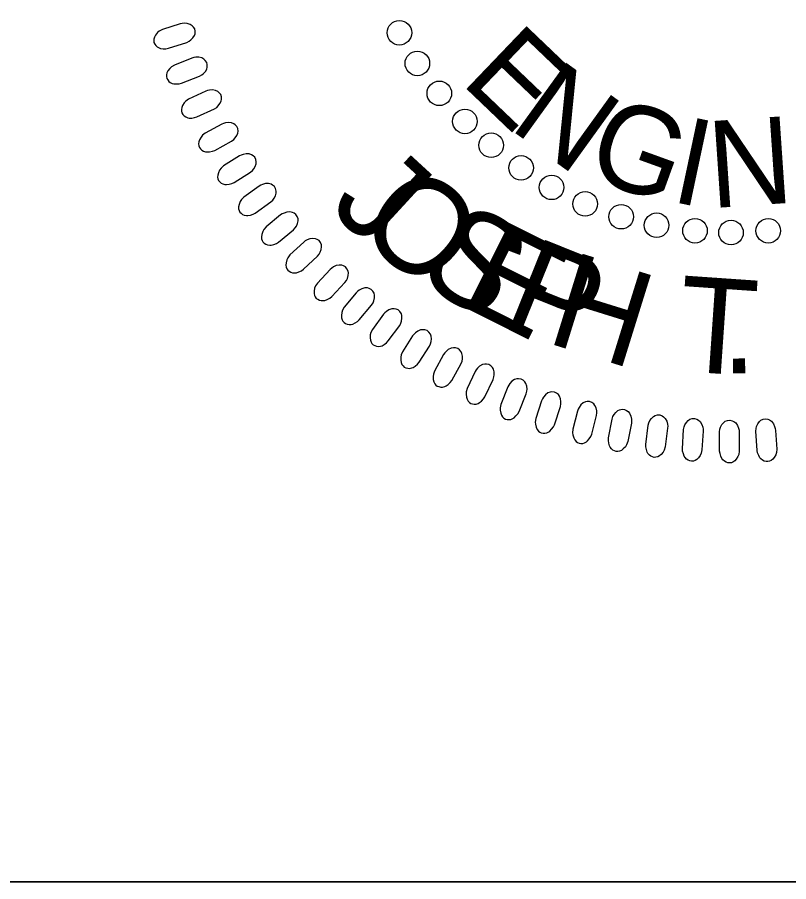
# Model space of a CAD drawing. Extents: x 1487909 to 1489267, y 497866 to 499814.
# Drawn here: x 1489041.143 to 1489045.319, y 498441.698 to 498446.38 of the extents above; entities that cross this region are included whole.
import ezdxf

# ---------------------------------------------------------------- set-up
doc = ezdxf.new("R2010")
doc.units = 0
for name, color, linetype in [('Old_Level_9', 7, 'Continuous'), ('Sheet Sticker Exception Certification CELL', 7, 'Continuous'), ('Sheet Typical CELL', 7, 'Continuous')]:
    doc.layers.add(name, color=color, linetype=linetype)

msp = doc.modelspace()

# ---------------------------------------------------------------- linework, layer by layer
at = {"layer": 'Old_Level_9'}
for points in [[(1489042.0249, 498446.3449), (1489041.928, 498446.3134), (1489041.9116, 498446.3049), (1489041.9019, 498446.2972), (1489041.8914, 498446.284), (1489041.8853, 498446.2735), (1489041.8818, 498446.2626), (1489041.8814, 498446.2533), (1489041.8827, 498446.244), (1489041.8871, 498446.2357), (1489041.8926, 498446.227), (1489041.8999, 498446.2202), (1489041.9105, 498446.2146), (1489041.9183, 498446.2118), (1489041.9319, 498446.2104), (1489041.9476, 498446.2103), (1489041.9608, 498446.2126), (1489042.0602, 498446.2442), (1489042.0729, 498446.2503), (1489042.0828, 498446.2574), (1489042.0931, 498446.2686), (1489042.1012, 498446.281), (1489042.1051, 498446.2907), (1489042.1058, 498446.3046), (1489042.1035, 498446.317), (1489042.0965, 498446.3277), (1489042.0899, 498446.3347), (1489042.0788, 498446.3422), (1489042.0624, 498446.3473), (1489042.0465, 498446.348), (1489042.0355, 498446.347)], [(1489042.0878, 498446.1592), (1489041.9931, 498446.1218), (1489041.9773, 498446.1122), (1489041.9681, 498446.1039), (1489041.9585, 498446.0901), (1489041.953, 498446.0792), (1489041.9503, 498446.0681), (1489041.9504, 498446.0589), (1489041.9522, 498446.0495), (1489041.9572, 498446.0416), (1489041.9632, 498446.0332), (1489041.9709, 498446.027), (1489041.9819, 498446.0219), (1489041.9898, 498446.0197), (1489042.0035, 498446.0191), (1489042.0191, 498446.02), (1489042.0321, 498446.0231), (1489042.1294, 498446.0609), (1489042.1418, 498446.0678), (1489042.1512, 498446.0755), (1489042.1607, 498446.0873), (1489042.1681, 498446.1002), (1489042.1713, 498446.1102), (1489042.1711, 498446.1241), (1489042.1681, 498446.1363), (1489042.1605, 498446.1466), (1489042.1534, 498446.1531), (1489042.1418, 498446.1599), (1489042.1251, 498446.1639), (1489042.1092, 498446.1637), (1489042.0983, 498446.162)], [(1489042.1625, 498445.98), (1489042.0703, 498445.9367), (1489042.0552, 498445.9261), (1489042.0465, 498445.9173), (1489042.0378, 498445.9028), (1489042.0329, 498445.8916), (1489042.0309, 498445.8804), (1489042.0316, 498445.8711), (1489042.0341, 498445.862), (1489042.0396, 498445.8543), (1489042.0461, 498445.8464), (1489042.0542, 498445.8406), (1489042.0654, 498445.8363), (1489042.0735, 498445.8346), (1489042.0871, 498445.8348), (1489042.1027, 498445.8367), (1489042.1155, 498445.8406), (1489042.2102, 498445.8844), (1489042.2221, 498445.8922), (1489042.231, 498445.9004), (1489042.2398, 498445.9128), (1489042.2464, 498445.9261), (1489042.2489, 498445.9363), (1489042.2479, 498445.9502), (1489042.2441, 498445.9622), (1489042.2358, 498445.9719), (1489042.2283, 498445.978), (1489042.2164, 498445.9841), (1489042.1994, 498445.987), (1489042.1835, 498445.9858), (1489042.1728, 498445.9834)], [(1489042.2494, 498445.8016), (1489042.1601, 498445.7526), (1489042.1457, 498445.7411), (1489042.1376, 498445.7317), (1489042.1298, 498445.7168), (1489042.1257, 498445.7053), (1489042.1244, 498445.694), (1489042.1256, 498445.6848), (1489042.1287, 498445.6758), (1489042.1346, 498445.6685), (1489042.1416, 498445.661), (1489042.1501, 498445.6558), (1489042.1616, 498445.6522), (1489042.1697, 498445.651), (1489042.1833, 498445.6521), (1489042.1987, 498445.6549), (1489042.2113, 498445.6596), (1489042.303, 498445.7093), (1489042.3144, 498445.7177), (1489042.3228, 498445.7266), (1489042.3308, 498445.7395), (1489042.3364, 498445.7532), (1489042.3384, 498445.7635), (1489042.3365, 498445.7772), (1489042.3319, 498445.789), (1489042.323, 498445.7982), (1489042.3152, 498445.8039), (1489042.3029, 498445.8091), (1489042.2858, 498445.811), (1489042.27, 498445.8087), (1489042.2594, 498445.8057)], [(1489042.3454, 498445.6295), (1489042.2594, 498445.5749), (1489042.2457, 498445.5626), (1489042.2382, 498445.5527), (1489042.2313, 498445.5372), (1489042.2279, 498445.5256), (1489042.2273, 498445.5142), (1489042.2292, 498445.5051), (1489042.2328, 498445.4963), (1489042.2392, 498445.4894), (1489042.2466, 498445.4823), (1489042.2554, 498445.4776), (1489042.2671, 498445.4747), (1489042.2753, 498445.4741), (1489042.2888, 498445.476), (1489042.304, 498445.4798), (1489042.3162, 498445.4853), (1489042.4046, 498445.5406), (1489042.4155, 498445.5497), (1489042.4233, 498445.5592), (1489042.4305, 498445.5725), (1489042.4353, 498445.5866), (1489042.4366, 498445.5969), (1489042.4338, 498445.6106), (1489042.4285, 498445.622), (1489042.4191, 498445.6307), (1489042.411, 498445.6357), (1489042.3983, 498445.6403), (1489042.3811, 498445.6411), (1489042.3655, 498445.6378), (1489042.3551, 498445.6341)], [(1489042.4514, 498445.4655), (1489042.3689, 498445.4057), (1489042.356, 498445.3925), (1489042.3491, 498445.3822), (1489042.3433, 498445.3664), (1489042.3407, 498445.3545), (1489042.3408, 498445.3431), (1489042.3432, 498445.3341), (1489042.3473, 498445.3255), (1489042.3541, 498445.319), (1489042.362, 498445.3124), (1489042.3711, 498445.3083), (1489042.3829, 498445.3062), (1489042.3912, 498445.3061), (1489042.4045, 498445.3088), (1489042.4194, 498445.3136), (1489042.4313, 498445.3198), (1489042.516, 498445.3806), (1489042.5263, 498445.3904), (1489042.5335, 498445.4002), (1489042.5399, 498445.414), (1489042.5438, 498445.4283), (1489042.5444, 498445.4388), (1489042.5408, 498445.4522), (1489042.5348, 498445.4633), (1489042.5248, 498445.4713), (1489042.5164, 498445.4759), (1489042.5035, 498445.4797), (1489042.4863, 498445.4794), (1489042.4709, 498445.4751), (1489042.4608, 498445.4708)], [(1489042.5678, 498445.3094), (1489042.4893, 498445.2445), (1489042.4773, 498445.2305), (1489042.4711, 498445.2198), (1489042.4662, 498445.2036), (1489042.4643, 498445.1916), (1489042.4652, 498445.1802), (1489042.4681, 498445.1714), (1489042.4728, 498445.1632), (1489042.48, 498445.1571), (1489042.4883, 498445.151), (1489042.4976, 498445.1475), (1489042.5095, 498445.1461), (1489042.5178, 498445.1465), (1489042.5309, 498445.1501), (1489042.5455, 498445.1557), (1489042.5569, 498445.1627), (1489042.6378, 498445.2287), (1489042.6474, 498445.2391), (1489042.6539, 498445.2494), (1489042.6594, 498445.2635), (1489042.6624, 498445.2781), (1489042.6624, 498445.2885), (1489042.6579, 498445.3017), (1489042.6513, 498445.3124), (1489042.6408, 498445.3198), (1489042.6321, 498445.3238), (1489042.619, 498445.3267), (1489042.6018, 498445.3254), (1489042.5867, 498445.3202), (1489042.5769, 498445.3153)], [(1489042.6932, 498445.1624), (1489042.6189, 498445.0927), (1489042.6078, 498445.078), (1489042.6023, 498445.0669), (1489042.5984, 498445.0505), (1489042.5973, 498445.0384), (1489042.5988, 498445.0271), (1489042.6023, 498445.0184), (1489042.6075, 498445.0105), (1489042.6151, 498445.0049), (1489042.6237, 498444.9994), (1489042.6332, 498444.9964), (1489042.6452, 498444.9958), (1489042.6534, 498444.9967), (1489042.6664, 498445.0011), (1489042.6806, 498445.0077), (1489042.6915, 498445.0153), (1489042.768, 498445.0863), (1489042.777, 498445.0973), (1489042.7829, 498445.1079), (1489042.7875, 498445.1224), (1489042.7896, 498445.1371), (1489042.7888, 498445.1475), (1489042.7836, 498445.1605), (1489042.7762, 498445.1706), (1489042.7654, 498445.1774), (1489042.7564, 498445.1809), (1489042.7431, 498445.1829), (1489042.7261, 498445.1805), (1489042.7114, 498445.1744), (1489042.7019, 498445.1688)], [(1489042.8372, 498445.0148), (1489042.7675, 498444.9406), (1489042.7573, 498444.9252), (1489042.7525, 498444.9138), (1489042.7496, 498444.8972), (1489042.7493, 498444.8849), (1489042.7515, 498444.8738), (1489042.7556, 498444.8655), (1489042.7612, 498444.8579), (1489042.7691, 498444.8527), (1489042.7781, 498444.8477), (1489042.7878, 498444.8454), (1489042.7998, 498444.8455), (1489042.8079, 498444.8469), (1489042.8206, 498444.8521), (1489042.8343, 498444.8596), (1489042.8448, 498444.8679), (1489042.9167, 498444.9436), (1489042.9249, 498444.9551), (1489042.9302, 498444.9661), (1489042.9338, 498444.9808), (1489042.935, 498444.9956), (1489042.9336, 498445.006), (1489042.9276, 498445.0185), (1489042.9196, 498445.0283), (1489042.9083, 498445.0343), (1489042.8991, 498445.0372), (1489042.8858, 498445.0385), (1489042.8689, 498445.035), (1489042.8546, 498445.0279), (1489042.8454, 498445.0218)], [(1489042.9775, 498444.8878), (1489042.9125, 498444.8094), (1489042.9033, 498444.7933), (1489042.8992, 498444.7817), (1489042.8975, 498444.7649), (1489042.8979, 498444.7527), (1489042.9008, 498444.7417), (1489042.9054, 498444.7336), (1489042.9115, 498444.7263), (1489042.9197, 498444.7218), (1489042.929, 498444.7173), (1489042.9388, 498444.7156), (1489042.9508, 498444.7165), (1489042.9588, 498444.7184), (1489042.9711, 498444.7244), (1489042.9844, 498444.7327), (1489042.9943, 498444.7417), (1489043.0612, 498444.8217), (1489043.0688, 498444.8337), (1489043.0733, 498444.845), (1489043.076, 498444.8599), (1489043.0763, 498444.8748), (1489043.0742, 498444.8851), (1489043.0674, 498444.8972), (1489043.0588, 498444.9064), (1489043.0472, 498444.9117), (1489043.0378, 498444.9141), (1489043.0245, 498444.9144), (1489043.0079, 498444.9099), (1489042.994, 498444.902), (1489042.9853, 498444.8953)], [(1489043.1253, 498444.7716), (1489043.0654, 498444.6892), (1489043.0572, 498444.6726), (1489043.0539, 498444.6607), (1489043.0531, 498444.6438), (1489043.0544, 498444.6317), (1489043.058, 498444.6209), (1489043.063, 498444.6131), (1489043.0696, 498444.6063), (1489043.0781, 498444.6022), (1489043.0876, 498444.5984), (1489043.0976, 498444.5972), (1489043.1094, 498444.5989), (1489043.1173, 498444.6013), (1489043.1292, 498444.6081), (1489043.1419, 498444.6172), (1489043.1512, 498444.6268), (1489043.213, 498444.7108), (1489043.2198, 498444.7232), (1489043.2236, 498444.7349), (1489043.2254, 498444.7499), (1489043.2247, 498444.7648), (1489043.2221, 498444.7748), (1489043.2145, 498444.7866), (1489043.2054, 498444.7952), (1489043.1934, 498444.7998), (1489043.1839, 498444.8015), (1489043.1705, 498444.8011), (1489043.1543, 498444.7955), (1489043.1409, 498444.7867), (1489043.1326, 498444.7795)], [(1489043.2832, 498444.6543), (1489043.2286, 498444.5683), (1489043.2214, 498444.5513), (1489043.2188, 498444.5392), (1489043.2191, 498444.5223), (1489043.2211, 498444.5103), (1489043.2254, 498444.4997), (1489043.2309, 498444.4922), (1489043.2379, 498444.4859), (1489043.2466, 498444.4823), (1489043.2564, 498444.479), (1489043.2664, 498444.4786), (1489043.2781, 498444.4809), (1489043.2859, 498444.4839), (1489043.2973, 498444.4913), (1489043.3094, 498444.5012), (1489043.3181, 498444.5114), (1489043.3745, 498444.5991), (1489043.3805, 498444.612), (1489043.3835, 498444.6238), (1489043.3844, 498444.639), (1489043.3828, 498444.6537), (1489043.3794, 498444.6637), (1489043.3712, 498444.6749), (1489043.3616, 498444.6829), (1489043.3493, 498444.6867), (1489043.3397, 498444.6879), (1489043.3264, 498444.6866), (1489043.3105, 498444.68), (1489043.2978, 498444.6704), (1489043.2899, 498444.6627)], [(1489043.4506, 498444.5534), (1489043.4015, 498444.4642), (1489043.3955, 498444.4467), (1489043.3937, 498444.4345), (1489043.3951, 498444.4177), (1489043.3977, 498444.4058), (1489043.4027, 498444.3955), (1489043.4087, 498444.3884), (1489043.4161, 498444.3825), (1489043.425, 498444.3795), (1489043.4349, 498444.3768), (1489043.4449, 498444.3769), (1489043.4565, 498444.3801), (1489043.464, 498444.3834), (1489043.475, 498444.3917), (1489043.4865, 498444.4023), (1489043.4945, 498444.413), (1489043.5453, 498444.5041), (1489043.5504, 498444.5173), (1489043.5528, 498444.5293), (1489043.5526, 498444.5445), (1489043.5501, 498444.5591), (1489043.5462, 498444.5688), (1489043.5372, 498444.5794), (1489043.5271, 498444.5869), (1489043.5147, 498444.5899), (1489043.505, 498444.5905), (1489043.4918, 498444.5884), (1489043.4763, 498444.5808), (1489043.4642, 498444.5704), (1489043.4569, 498444.5622)], [(1489043.6216, 498444.4615), (1489043.5782, 498444.3694), (1489043.5732, 498444.3516), (1489043.5722, 498444.3393), (1489043.5746, 498444.3226), (1489043.578, 498444.3109), (1489043.5837, 498444.301), (1489043.5901, 498444.2943), (1489043.5978, 498444.2888), (1489043.6069, 498444.2864), (1489043.617, 498444.2844), (1489043.6269, 498444.2851), (1489043.6384, 498444.289), (1489043.6457, 498444.2928), (1489043.656, 498444.3017), (1489043.6669, 498444.313), (1489043.6742, 498444.3242), (1489043.7192, 498444.4183), (1489043.7235, 498444.4319), (1489043.725, 498444.4439), (1489043.724, 498444.4591), (1489043.7205, 498444.4735), (1489043.716, 498444.4829), (1489043.7063, 498444.493), (1489043.6958, 498444.4998), (1489043.6832, 498444.5021), (1489043.6735, 498444.502), (1489043.6605, 498444.4991), (1489043.6455, 498444.4905), (1489043.6341, 498444.4794), (1489043.6273, 498444.4707)], [(1489043.7982, 498444.3779), (1489043.7606, 498444.2832), (1489043.7568, 498444.2651), (1489043.7565, 498444.2528), (1489043.76, 498444.2362), (1489043.7641, 498444.2248), (1489043.7704, 498444.2152), (1489043.7772, 498444.2089), (1489043.7853, 498444.2039), (1489043.7945, 498444.2021), (1489043.8047, 498444.2007), (1489043.8146, 498444.2021), (1489043.8257, 498444.2067), (1489043.8328, 498444.211), (1489043.8425, 498444.2205), (1489043.8526, 498444.2325), (1489043.8593, 498444.2441), (1489043.8983, 498444.3408), (1489043.9017, 498444.3546), (1489043.9025, 498444.3667), (1489043.9005, 498444.3818), (1489043.8961, 498444.396), (1489043.891, 498444.4051), (1489043.8808, 498444.4146), (1489043.8698, 498444.4207), (1489043.8571, 498444.4221), (1489043.8475, 498444.4215), (1489043.8346, 498444.4177), (1489043.8202, 498444.4083), (1489043.8095, 498444.3964), (1489043.8033, 498444.3874)], [(1489043.9815, 498444.303), (1489043.95, 498444.2062), (1489043.9473, 498444.1879), (1489043.9478, 498444.1755), (1489043.9523, 498444.1592), (1489043.9571, 498444.1481), (1489043.964, 498444.1389), (1489043.9712, 498444.1331), (1489043.9795, 498444.1286), (1489043.9889, 498444.1274), (1489043.9991, 498444.1266), (1489044.0089, 498444.1286), (1489044.0197, 498444.1339), (1489044.0265, 498444.1386), (1489044.0357, 498444.1487), (1489044.045, 498444.1613), (1489044.0509, 498444.1733), (1489044.0837, 498444.2723), (1489044.0863, 498444.2863), (1489044.0863, 498444.2985), (1489044.0833, 498444.3133), (1489044.0781, 498444.3272), (1489044.0724, 498444.3361), (1489044.0616, 498444.3448), (1489044.0503, 498444.3502), (1489044.0375, 498444.3509), (1489044.0279, 498444.3496), (1489044.0153, 498444.3451), (1489044.0016, 498444.3347), (1489043.9916, 498444.3223), (1489043.986, 498444.3128)], [(1489044.1751, 498444.2471), (1489044.1497, 498444.1485), (1489044.1482, 498444.1302), (1489044.1495, 498444.1178), (1489044.155, 498444.1018), (1489044.1605, 498444.091), (1489044.168, 498444.0823), (1489044.1755, 498444.0769), (1489044.1841, 498444.073), (1489044.1935, 498444.0723), (1489044.2038, 498444.0723), (1489044.2134, 498444.0748), (1489044.2239, 498444.0807), (1489044.2304, 498444.0859), (1489044.2388, 498444.0965), (1489044.2474, 498444.1097), (1489044.2525, 498444.1221), (1489044.2791, 498444.2229), (1489044.2807, 498444.237), (1489044.28, 498444.2492), (1489044.2761, 498444.2639), (1489044.27, 498444.2774), (1489044.2638, 498444.2858), (1489044.2524, 498444.2939), (1489044.2408, 498444.2986), (1489044.2279, 498444.2985), (1489044.2185, 498444.2966), (1489044.2062, 498444.2913), (1489044.1932, 498444.2801), (1489044.184, 498444.267), (1489044.179, 498444.2572)], [(1489044.4674, 498444.1818), (1489044.4483, 498444.0817), (1489044.4418, 498444.0644), (1489044.4354, 498444.0538), (1489044.4236, 498444.0418), (1489044.414, 498444.0344), (1489044.4036, 498444.0296), (1489044.3945, 498444.028), (1489044.385, 498444.0281), (1489044.3762, 498444.0315), (1489044.3669, 498444.0358), (1489044.3593, 498444.0423), (1489044.3523, 498444.052), (1489044.3487, 498444.0595), (1489044.3455, 498444.0727), (1489044.3434, 498444.0883), (1489044.3441, 498444.1017), (1489044.3631, 498444.2042), (1489044.3676, 498444.2177), (1489044.3734, 498444.2284), (1489044.3832, 498444.24), (1489044.3945, 498444.2496), (1489044.4037, 498444.2546), (1489044.4173, 498444.257), (1489044.4299, 498444.2563), (1489044.4414, 498444.2507), (1489044.4492, 498444.245), (1489044.458, 498444.235), (1489044.4651, 498444.2193), (1489044.4678, 498444.2036), (1489044.4682, 498444.1926)], [(1489044.6638, 498444.1547), (1489044.651, 498444.0537), (1489044.6456, 498444.036), (1489044.6399, 498444.025), (1489044.6289, 498444.0122), (1489044.6197, 498444.0042), (1489044.6097, 498443.9988), (1489044.6006, 498443.9966), (1489044.5912, 498443.9962), (1489044.5822, 498443.999), (1489044.5726, 498444.0027), (1489044.5646, 498444.0087), (1489044.5571, 498444.018), (1489044.553, 498444.0252), (1489044.549, 498444.0383), (1489044.5459, 498444.0536), (1489044.5458, 498444.067), (1489044.5582, 498444.1705), (1489044.5619, 498444.1842), (1489044.5671, 498444.1953), (1489044.576, 498444.2075), (1489044.5867, 498444.2178), (1489044.5956, 498444.2234), (1489044.6091, 498444.2267), (1489044.6217, 498444.2267), (1489044.6335, 498444.2219), (1489044.6417, 498444.2167), (1489044.6511, 498444.2072), (1489044.6591, 498444.192), (1489044.6628, 498444.1765), (1489044.6639, 498444.1655)], [(1489044.8561, 498444.1383), (1489044.8497, 498444.0367), (1489044.8455, 498444.0187), (1489044.8404, 498444.0074), (1489044.8302, 498443.9939), (1489044.8216, 498443.9853), (1489044.8119, 498443.9794), (1489044.803, 498443.9766), (1489044.7936, 498443.9755), (1489044.7845, 498443.9778), (1489044.7747, 498443.9809), (1489044.7664, 498443.9863), (1489044.7582, 498443.9952), (1489044.7536, 498444.0021), (1489044.7489, 498444.0149), (1489044.7448, 498444.03), (1489044.7438, 498444.0434), (1489044.7498, 498444.1475), (1489044.7525, 498444.1614), (1489044.757, 498444.1728), (1489044.7653, 498444.1855), (1489044.7752, 498444.1965), (1489044.7838, 498444.2026), (1489044.797, 498444.2067), (1489044.8096, 498444.2076), (1489044.8217, 498444.2035), (1489044.8301, 498444.1988), (1489044.8401, 498444.1899), (1489044.8491, 498444.1752), (1489044.8538, 498444.1599), (1489044.8556, 498444.1491)], [(1489045.0515, 498444.1323), (1489045.0514, 498444.0305), (1489045.0483, 498444.0123), (1489045.044, 498444.0007), (1489045.0347, 498443.9866), (1489045.0266, 498443.9775), (1489045.0172, 498443.9709), (1489045.0086, 498443.9676), (1489044.9993, 498443.966), (1489044.99, 498443.9676), (1489044.98, 498443.9701), (1489044.9713, 498443.975), (1489044.9627, 498443.9834), (1489044.9577, 498443.99), (1489044.9521, 498444.0024), (1489044.9472, 498444.0173), (1489044.9453, 498444.0305), (1489044.9447, 498444.1348), (1489044.9466, 498444.1489), (1489044.9503, 498444.1605), (1489044.9578, 498444.1737), (1489044.9671, 498444.1853), (1489044.9752, 498444.192), (1489044.9882, 498444.1969), (1489045.0006, 498444.1985), (1489045.013, 498444.1952), (1489045.0217, 498444.1911), (1489045.0323, 498444.1829), (1489045.0421, 498444.1688), (1489045.0478, 498444.1538), (1489045.0502, 498444.1431)], [(1489045.2479, 498444.1425), (1489045.2542, 498444.0408), (1489045.2523, 498444.0225), (1489045.2488, 498444.0107), (1489045.2403, 498443.996), (1489045.2329, 498443.9864), (1489045.2239, 498443.9793), (1489045.2155, 498443.9754), (1489045.2063, 498443.9732), (1489045.197, 498443.9743), (1489045.1869, 498443.9761), (1489045.1779, 498443.9805), (1489045.1687, 498443.9883), (1489045.1633, 498443.9945), (1489045.157, 498444.0066), (1489045.1511, 498444.0212), (1489045.1484, 498444.0343), (1489045.1413, 498444.1383), (1489045.1422, 498444.1525), (1489045.1453, 498444.1643), (1489045.1519, 498444.1779), (1489045.1604, 498444.1901), (1489045.1681, 498444.1972), (1489045.1807, 498444.203), (1489045.1931, 498444.2054), (1489045.2056, 498444.2029), (1489045.2145, 498444.1993), (1489045.2256, 498444.1917), (1489045.2364, 498444.1782), (1489045.2429, 498444.1637), (1489045.246, 498444.1532)]]:
    msp.add_lwpolyline(points, close=True, dxfattribs=at)
for centre in [(1489043.2116, 498446.2968), (1489043.3086, 498446.1304), (1489043.4275, 498445.9684), (1489043.5662, 498445.8162), (1489043.7083, 498445.6872), (1489043.8702, 498445.5648), (1489044.0353, 498445.459), (1489044.2171, 498445.3697), (1489044.412, 498445.3002), (1489044.6037, 498445.2538), (1489044.8118, 498445.224), (1489045.0068, 498445.214), (1489045.2084, 498445.2238)]:
    msp.add_circle(centre, 0.0665, dxfattribs=at)
at = {"layer": 'Sheet Sticker Exception Certification CELL'}
msp.add_line((1489029.9586, 498441.6976), (1489049.9623, 498441.6976), dxfattribs=at)
at = {"layer": 'Sheet Typical CELL'}
msp.add_lwpolyline([(1489039.9636, 498452.9476), (1489049.9636, 498452.9476), (1489049.9636, 498441.6976), (1489039.9636, 498441.6976)], close=True, dxfattribs=at)

# ---------------------------------------------------------------- texts
at = {"layer": 'Old_Level_9'}
for s, height, rotation, p in [('E', 0.4706, 316.2656, (1489043.5371, 498446.028)), ('N', 0.4706, 324.2054, (1489043.7973, 498445.7827)), ('G', 0.4706, 340.085, (1489044.2036, 498445.5255)), ('I', 0.4706, 348.0248, (1489044.6707, 498445.3853)), ('N', 0.4706, 3.9044, (1489044.8992, 498445.3461)), ('J', 0.5176, 317.4307, (1489042.8207, 498445.346)), ('O', 0.5176, 320.8973, (1489042.9611, 498445.217)), ('S', 0.5176, 328.5195, (1489043.2955, 498444.9647)), ('E', 0.5176, 333.3496, (1489043.5237, 498444.8288)), ('P', 0.5176, 338.037, (1489043.7552, 498444.7156)), ('H', 0.5176, 342.7244, (1489043.9953, 498444.6218)), ('T', 0.5176, 356.0326, (1489044.7087, 498444.4655)), ('.', 0.5176, 0.5162, (1489044.9547, 498444.4507))]:
    msp.add_text(s, height=height, rotation=rotation, dxfattribs=at).set_placement(p)

doc.saveas('drawing.dxf')
